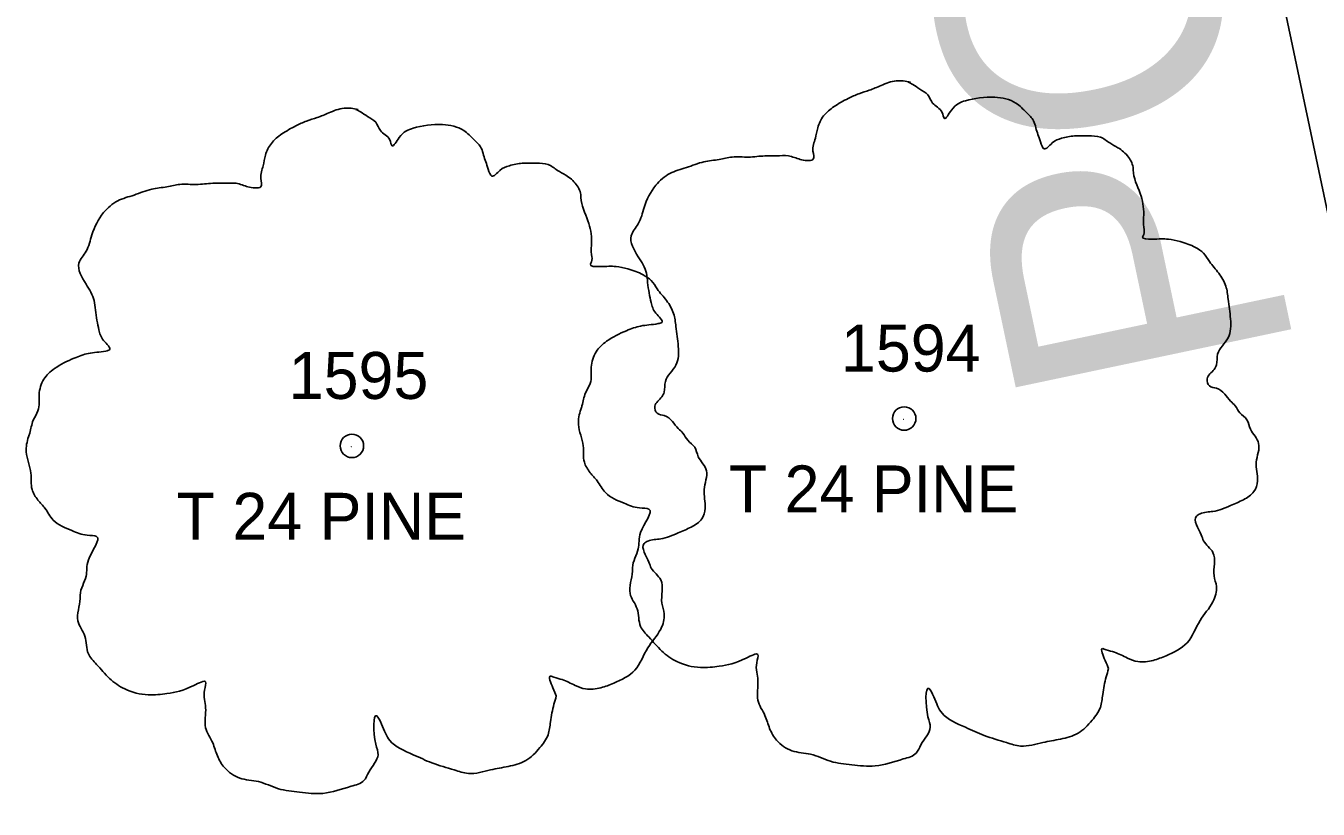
# Model space of a CAD drawing. Extents: x 1964982 to 1970452, y 1116335 to 1119906.
# Drawn here: x 1966642.81 to 1966670.35, y 1117477.18 to 1117493.86 of the extents above; entities that cross this region are included whole.
import ezdxf

# ---------------------------------------------------------------- set-up
doc = ezdxf.new("R2010")
doc.units = 0
for name, color, linetype in [('RD_EX_VEG', 7, 'Continuous'), ('RD_EX_VEG_txCode', 7, 'Continuous'), ('RD_HC_Data', 7, 'Continuous')]:
    doc.layers.add(name, color=color, linetype=linetype)

msp = doc.modelspace()

# ---------------------------------------------------------------- linework, layer by layer
at = {"layer": 'RD_EX_VEG'}
for centre, radius in [((1966661.529, 1117485.495), 0.25), ((1966661.529, 1117485.495), 0.25), ((1966661.516, 1117485.476), 0.0001), ((1966661.516, 1117485.476), 0.0001), ((1966649.762, 1117484.912), 0.25), ((1966649.762, 1117484.912), 0.25), ((1966649.749, 1117484.893), 0.0001), ((1966649.749, 1117484.893), 0.0001)]:
    msp.add_circle(centre, radius, dxfattribs=at)
for points in [[(1966661.661, 1117492.662), (1966661.361, 1117492.687), (1966661.036, 1117492.587), (1966660.786, 1117492.487), (1966660.561, 1117492.412), (1966660.336, 1117492.312), (1966660.036, 1117492.138), (1966659.811, 1117491.938), (1966659.686, 1117491.688), (1966659.636, 1117491.463), (1966659.586, 1117491.188), (1966659.586, 1117491.013), (1966659.462, 1117490.988), (1966659.312, 1117491.013), (1966659.062, 1117491.088), (1966658.812, 1117491.088), (1966658.562, 1117491.088), (1966658.212, 1117491.063), (1966657.862, 1117491.063), (1966657.587, 1117491.013), (1966657.262, 1117490.963), (1966656.888, 1117490.838), (1966656.538, 1117490.713), (1966656.238, 1117490.463), (1966655.988, 1117489.989), (1966655.863, 1117489.639), (1966655.713, 1117489.389), (1966655.863, 1117488.939), (1966656.038, 1117488.589), (1966656.063, 1117488.389), (1966656.138, 1117487.964), (1966656.238, 1117487.74), (1966656.363, 1117487.54), (1966656.288, 1117487.515), (1966655.913, 1117487.465), (1966655.613, 1117487.365), (1966655.188, 1117487.14), (1966654.963, 1117486.915), (1966654.863, 1117486.59), (1966654.839, 1117486.24), (1966654.739, 1117486.04), (1966654.664, 1117485.765), (1966654.639, 1117485.69), (1966654.589, 1117485.366), (1966654.689, 1117484.916), (1966654.714, 1117484.566), (1966654.839, 1117484.341), (1966654.988, 1117484.166), (1966655.163, 1117483.916), (1966655.563, 1117483.691), (1966655.888, 1117483.591), (1966656.088, 1117483.566), (1966655.913, 1117483.067), (1966655.863, 1117482.717), (1966655.738, 1117482.317), (1966655.738, 1117482.242), (1966655.688, 1117481.767), (1966655.838, 1117481.442), (1966655.913, 1117481.067), (1966656.088, 1117480.843), (1966656.363, 1117480.543), (1966656.688, 1117480.318), (1966657.188, 1117480.193), (1966657.587, 1117480.218), (1966658.162, 1117480.393), (1966658.412, 1117480.468), (1966658.387, 1117480.293), (1966658.412, 1117479.918), (1966658.412, 1117479.493), (1966658.562, 1117479.168), (1966658.662, 1117478.893), (1966658.812, 1117478.643), (1966659.137, 1117478.419), (1966659.536, 1117478.344), (1966659.961, 1117478.194), (1966660.411, 1117478.119), (1966660.911, 1117478.094), (1966661.511, 1117478.244), (1966661.785, 1117478.369), (1966661.885, 1117478.544), (1966662.085, 1117478.918), (1966662.035, 1117479.143), (1966662.06, 1117479.743), (1966662.16, 1117479.568), (1966662.335, 1117479.218), (1966662.835, 1117478.918), (1966663.235, 1117478.743), (1966663.71, 1117478.593), (1966664.01, 1117478.519), (1966664.484, 1117478.593), (1966664.859, 1117478.668), (1966665.234, 1117478.793), (1966665.534, 1117479.068), (1966665.709, 1117479.343), (1966665.759, 1117479.618), (1966665.834, 1117479.993), (1966665.884, 1117480.168)], [(1966661.661, 1117492.662), (1966661.361, 1117492.687), (1966661.036, 1117492.587), (1966660.786, 1117492.487), (1966660.561, 1117492.412), (1966660.336, 1117492.312), (1966660.036, 1117492.138), (1966659.811, 1117491.938), (1966659.686, 1117491.688), (1966659.636, 1117491.463), (1966659.586, 1117491.188), (1966659.586, 1117491.013), (1966659.462, 1117490.988), (1966659.312, 1117491.013), (1966659.062, 1117491.088), (1966658.812, 1117491.088), (1966658.562, 1117491.088), (1966658.212, 1117491.063), (1966657.862, 1117491.063), (1966657.587, 1117491.013), (1966657.262, 1117490.963), (1966656.888, 1117490.838), (1966656.538, 1117490.713), (1966656.238, 1117490.463), (1966655.988, 1117489.989), (1966655.863, 1117489.639), (1966655.713, 1117489.389), (1966655.863, 1117488.939), (1966656.038, 1117488.589), (1966656.063, 1117488.389), (1966656.138, 1117487.964), (1966656.238, 1117487.74), (1966656.363, 1117487.54), (1966656.288, 1117487.515), (1966655.913, 1117487.465), (1966655.613, 1117487.365), (1966655.188, 1117487.14), (1966654.963, 1117486.915), (1966654.863, 1117486.59), (1966654.839, 1117486.24), (1966654.739, 1117486.04), (1966654.664, 1117485.765), (1966654.639, 1117485.69), (1966654.589, 1117485.366), (1966654.689, 1117484.916), (1966654.714, 1117484.566), (1966654.839, 1117484.341), (1966654.988, 1117484.166), (1966655.163, 1117483.916), (1966655.563, 1117483.691), (1966655.888, 1117483.591), (1966656.088, 1117483.566), (1966655.913, 1117483.067), (1966655.863, 1117482.717), (1966655.738, 1117482.317), (1966655.738, 1117482.242), (1966655.688, 1117481.767), (1966655.838, 1117481.442), (1966655.913, 1117481.067), (1966656.088, 1117480.843), (1966656.363, 1117480.543), (1966656.688, 1117480.318), (1966657.188, 1117480.193), (1966657.587, 1117480.218), (1966658.162, 1117480.393), (1966658.412, 1117480.468), (1966658.387, 1117480.293), (1966658.412, 1117479.918), (1966658.412, 1117479.493), (1966658.562, 1117479.168), (1966658.662, 1117478.893), (1966658.812, 1117478.643), (1966659.137, 1117478.419), (1966659.536, 1117478.344), (1966659.961, 1117478.194), (1966660.411, 1117478.119), (1966660.911, 1117478.094), (1966661.511, 1117478.244), (1966661.785, 1117478.369), (1966661.885, 1117478.544), (1966662.085, 1117478.918), (1966662.035, 1117479.143), (1966662.06, 1117479.743), (1966662.16, 1117479.568), (1966662.335, 1117479.218), (1966662.835, 1117478.918), (1966663.235, 1117478.743), (1966663.71, 1117478.593), (1966664.01, 1117478.519), (1966664.484, 1117478.593), (1966664.859, 1117478.668), (1966665.234, 1117478.793), (1966665.534, 1117479.068), (1966665.709, 1117479.343), (1966665.759, 1117479.618), (1966665.834, 1117479.993), (1966665.884, 1117480.168)], [(1966665.884, 1117480.168), (1966665.809, 1117480.343), (1966665.759, 1117480.593), (1966665.834, 1117480.568), (1966666.009, 1117480.518), (1966666.284, 1117480.393), (1966666.508, 1117480.318), (1966666.833, 1117480.343), (1966667.108, 1117480.443), (1966667.558, 1117480.718), (1966667.833, 1117481.192), (1966668.108, 1117481.592), (1966668.183, 1117481.917), (1966668.133, 1117482.142), (1966668.108, 1117482.642), (1966667.908, 1117482.892), (1966667.858, 1117483.017), (1966667.758, 1117483.416), (1966667.833, 1117483.466), (1966668.108, 1117483.516), (1966668.483, 1117483.641), (1966668.757, 1117483.766), (1966668.982, 1117483.941), (1966669.057, 1117484.166), (1966669.032, 1117484.566), (1966669.082, 1117484.966), (1966669.007, 1117485.116), (1966668.907, 1117485.266), (1966668.832, 1117485.466), (1966668.682, 1117485.615), (1966668.583, 1117485.765), (1966668.483, 1117485.865), (1966668.358, 1117486.015), (1966668.183, 1117486.14), (1966668.033, 1117486.19), (1966667.983, 1117486.34), (1966668.133, 1117486.54), (1966668.183, 1117486.64), (1966668.208, 1117486.865), (1966668.433, 1117487.215), (1966668.483, 1117487.615), (1966668.433, 1117488.039), (1966668.383, 1117488.314), (1966668.233, 1117488.589), (1966668.033, 1117488.839), (1966667.908, 1117489.014), (1966667.733, 1117489.139), (1966667.408, 1117489.264), (1966667.158, 1117489.314), (1966666.808, 1117489.314), (1966666.608, 1117489.364), (1966666.633, 1117489.414), (1966666.633, 1117489.564), (1966666.633, 1117489.839), (1966666.558, 1117490.288), (1966666.408, 1117490.788), (1966666.408, 1117490.813), (1966666.308, 1117491.063), (1966666.084, 1117491.263), (1966665.909, 1117491.363), (1966665.709, 1117491.488), (1966665.459, 1117491.513), (1966665.159, 1117491.513), (1966664.884, 1117491.463), (1966664.684, 1117491.363), (1966664.509, 1117491.238), (1966664.434, 1117491.388), (1966664.334, 1117491.688), (1966664.284, 1117491.838), (1966664.134, 1117492.013), (1966663.91, 1117492.213), (1966663.46, 1117492.337), (1966662.835, 1117492.263), (1966662.535, 1117492.063), (1966662.385, 1117491.888), (1966662.335, 1117492.013), (1966662.135, 1117492.213), (1966662.035, 1117492.387), (1966661.86, 1117492.512), (1966661.711, 1117492.612), (1966661.611, 1117492.662)], [(1966665.884, 1117480.168), (1966665.809, 1117480.343), (1966665.759, 1117480.593), (1966665.834, 1117480.568), (1966666.009, 1117480.518), (1966666.284, 1117480.393), (1966666.508, 1117480.318), (1966666.833, 1117480.343), (1966667.108, 1117480.443), (1966667.558, 1117480.718), (1966667.833, 1117481.192), (1966668.108, 1117481.592), (1966668.183, 1117481.917), (1966668.133, 1117482.142), (1966668.108, 1117482.642), (1966667.908, 1117482.892), (1966667.858, 1117483.017), (1966667.758, 1117483.416), (1966667.833, 1117483.466), (1966668.108, 1117483.516), (1966668.483, 1117483.641), (1966668.757, 1117483.766), (1966668.982, 1117483.941), (1966669.057, 1117484.166), (1966669.032, 1117484.566), (1966669.082, 1117484.966), (1966669.007, 1117485.116), (1966668.907, 1117485.266), (1966668.832, 1117485.466), (1966668.682, 1117485.615), (1966668.583, 1117485.765), (1966668.483, 1117485.865), (1966668.358, 1117486.015), (1966668.183, 1117486.14), (1966668.033, 1117486.19), (1966667.983, 1117486.34), (1966668.133, 1117486.54), (1966668.183, 1117486.64), (1966668.208, 1117486.865), (1966668.433, 1117487.215), (1966668.483, 1117487.615), (1966668.433, 1117488.039), (1966668.383, 1117488.314), (1966668.233, 1117488.589), (1966668.033, 1117488.839), (1966667.908, 1117489.014), (1966667.733, 1117489.139), (1966667.408, 1117489.264), (1966667.158, 1117489.314), (1966666.808, 1117489.314), (1966666.608, 1117489.364), (1966666.633, 1117489.414), (1966666.633, 1117489.564), (1966666.633, 1117489.839), (1966666.558, 1117490.288), (1966666.408, 1117490.788), (1966666.408, 1117490.813), (1966666.308, 1117491.063), (1966666.084, 1117491.263), (1966665.909, 1117491.363), (1966665.709, 1117491.488), (1966665.459, 1117491.513), (1966665.159, 1117491.513), (1966664.884, 1117491.463), (1966664.684, 1117491.363), (1966664.509, 1117491.238), (1966664.434, 1117491.388), (1966664.334, 1117491.688), (1966664.284, 1117491.838), (1966664.134, 1117492.013), (1966663.91, 1117492.213), (1966663.46, 1117492.337), (1966662.835, 1117492.263), (1966662.535, 1117492.063), (1966662.385, 1117491.888), (1966662.335, 1117492.013), (1966662.135, 1117492.213), (1966662.035, 1117492.387), (1966661.86, 1117492.512), (1966661.711, 1117492.612), (1966661.611, 1117492.662)], [(1966649.894, 1117492.079), (1966649.594, 1117492.104), (1966649.269, 1117492.004), (1966649.019, 1117491.904), (1966648.794, 1117491.829), (1966648.569, 1117491.729), (1966648.269, 1117491.555), (1966648.045, 1117491.355), (1966647.92, 1117491.105), (1966647.87, 1117490.88), (1966647.82, 1117490.605), (1966647.82, 1117490.43), (1966647.695, 1117490.405), (1966647.545, 1117490.43), (1966647.295, 1117490.505), (1966647.045, 1117490.505), (1966646.795, 1117490.505), (1966646.445, 1117490.48), (1966646.095, 1117490.48), (1966645.821, 1117490.43), (1966645.496, 1117490.38), (1966645.121, 1117490.255), (1966644.771, 1117490.13), (1966644.471, 1117489.88), (1966644.221, 1117489.405), (1966644.096, 1117489.056), (1966643.946, 1117488.806), (1966644.096, 1117488.356), (1966644.271, 1117488.006), (1966644.296, 1117487.806), (1966644.371, 1117487.381), (1966644.471, 1117487.156), (1966644.596, 1117486.956), (1966644.521, 1117486.932), (1966644.146, 1117486.882), (1966643.846, 1117486.782), (1966643.422, 1117486.557), (1966643.197, 1117486.332), (1966643.097, 1117486.007), (1966643.072, 1117485.657), (1966642.972, 1117485.457), (1966642.897, 1117485.182), (1966642.872, 1117485.107), (1966642.822, 1117484.782), (1966642.922, 1117484.333), (1966642.947, 1117483.983), (1966643.072, 1117483.758), (1966643.222, 1117483.583), (1966643.397, 1117483.333), (1966643.796, 1117483.108), (1966644.121, 1117483.008), (1966644.321, 1117482.983), (1966644.146, 1117482.483), (1966644.096, 1117482.134), (1966643.971, 1117481.734), (1966643.971, 1117481.659), (1966643.921, 1117481.184), (1966644.071, 1117480.859), (1966644.146, 1117480.484), (1966644.321, 1117480.259), (1966644.596, 1117479.96), (1966644.921, 1117479.735), (1966645.421, 1117479.61), (1966645.821, 1117479.635), (1966646.395, 1117479.81), (1966646.645, 1117479.885), (1966646.62, 1117479.71), (1966646.645, 1117479.335), (1966646.645, 1117478.91), (1966646.795, 1117478.585), (1966646.895, 1117478.31), (1966647.045, 1117478.06), (1966647.37, 1117477.836), (1966647.77, 1117477.761), (1966648.194, 1117477.611), (1966648.644, 1117477.536), (1966649.144, 1117477.511), (1966649.744, 1117477.661), (1966650.019, 1117477.786), (1966650.119, 1117477.96), (1966650.319, 1117478.335), (1966650.269, 1117478.56), (1966650.294, 1117479.16), (1966650.393, 1117478.985), (1966650.568, 1117478.635), (1966651.068, 1117478.335), (1966651.468, 1117478.16), (1966651.943, 1117478.01), (1966652.243, 1117477.935), (1966652.717, 1117478.01), (1966653.092, 1117478.085), (1966653.467, 1117478.21), (1966653.767, 1117478.485), (1966653.942, 1117478.76), (1966653.992, 1117479.035), (1966654.067, 1117479.41), (1966654.117, 1117479.585)], [(1966649.894, 1117492.079), (1966649.594, 1117492.104), (1966649.269, 1117492.004), (1966649.019, 1117491.904), (1966648.794, 1117491.829), (1966648.569, 1117491.729), (1966648.269, 1117491.555), (1966648.045, 1117491.355), (1966647.92, 1117491.105), (1966647.87, 1117490.88), (1966647.82, 1117490.605), (1966647.82, 1117490.43), (1966647.695, 1117490.405), (1966647.545, 1117490.43), (1966647.295, 1117490.505), (1966647.045, 1117490.505), (1966646.795, 1117490.505), (1966646.445, 1117490.48), (1966646.095, 1117490.48), (1966645.821, 1117490.43), (1966645.496, 1117490.38), (1966645.121, 1117490.255), (1966644.771, 1117490.13), (1966644.471, 1117489.88), (1966644.221, 1117489.405), (1966644.096, 1117489.056), (1966643.946, 1117488.806), (1966644.096, 1117488.356), (1966644.271, 1117488.006), (1966644.296, 1117487.806), (1966644.371, 1117487.381), (1966644.471, 1117487.156), (1966644.596, 1117486.956), (1966644.521, 1117486.932), (1966644.146, 1117486.882), (1966643.846, 1117486.782), (1966643.422, 1117486.557), (1966643.197, 1117486.332), (1966643.097, 1117486.007), (1966643.072, 1117485.657), (1966642.972, 1117485.457), (1966642.897, 1117485.182), (1966642.872, 1117485.107), (1966642.822, 1117484.782), (1966642.922, 1117484.333), (1966642.947, 1117483.983), (1966643.072, 1117483.758), (1966643.222, 1117483.583), (1966643.397, 1117483.333), (1966643.796, 1117483.108), (1966644.121, 1117483.008), (1966644.321, 1117482.983), (1966644.146, 1117482.483), (1966644.096, 1117482.134), (1966643.971, 1117481.734), (1966643.971, 1117481.659), (1966643.921, 1117481.184), (1966644.071, 1117480.859), (1966644.146, 1117480.484), (1966644.321, 1117480.259), (1966644.596, 1117479.96), (1966644.921, 1117479.735), (1966645.421, 1117479.61), (1966645.821, 1117479.635), (1966646.395, 1117479.81), (1966646.645, 1117479.885), (1966646.62, 1117479.71), (1966646.645, 1117479.335), (1966646.645, 1117478.91), (1966646.795, 1117478.585), (1966646.895, 1117478.31), (1966647.045, 1117478.06), (1966647.37, 1117477.836), (1966647.77, 1117477.761), (1966648.194, 1117477.611), (1966648.644, 1117477.536), (1966649.144, 1117477.511), (1966649.744, 1117477.661), (1966650.019, 1117477.786), (1966650.119, 1117477.96), (1966650.319, 1117478.335), (1966650.269, 1117478.56), (1966650.294, 1117479.16), (1966650.393, 1117478.985), (1966650.568, 1117478.635), (1966651.068, 1117478.335), (1966651.468, 1117478.16), (1966651.943, 1117478.01), (1966652.243, 1117477.935), (1966652.717, 1117478.01), (1966653.092, 1117478.085), (1966653.467, 1117478.21), (1966653.767, 1117478.485), (1966653.942, 1117478.76), (1966653.992, 1117479.035), (1966654.067, 1117479.41), (1966654.117, 1117479.585)], [(1966654.117, 1117479.585), (1966654.042, 1117479.76), (1966653.992, 1117480.01), (1966654.067, 1117479.985), (1966654.242, 1117479.935), (1966654.517, 1117479.81), (1966654.742, 1117479.735), (1966655.066, 1117479.76), (1966655.341, 1117479.86), (1966655.791, 1117480.135), (1966656.066, 1117480.609), (1966656.341, 1117481.009), (1966656.416, 1117481.334), (1966656.366, 1117481.559), (1966656.341, 1117482.059), (1966656.141, 1117482.309), (1966656.091, 1117482.433), (1966655.991, 1117482.833), (1966656.066, 1117482.883), (1966656.341, 1117482.933), (1966656.716, 1117483.058), (1966656.991, 1117483.183), (1966657.216, 1117483.358), (1966657.29, 1117483.583), (1966657.266, 1117483.983), (1966657.315, 1117484.383), (1966657.241, 1117484.533), (1966657.141, 1117484.682), (1966657.066, 1117484.882), (1966656.916, 1117485.032), (1966656.816, 1117485.182), (1966656.716, 1117485.282), (1966656.591, 1117485.432), (1966656.416, 1117485.557), (1966656.266, 1117485.607), (1966656.216, 1117485.757), (1966656.366, 1117485.957), (1966656.416, 1117486.057), (1966656.441, 1117486.282), (1966656.666, 1117486.632), (1966656.716, 1117487.031), (1966656.666, 1117487.456), (1966656.616, 1117487.731), (1966656.466, 1117488.006), (1966656.266, 1117488.256), (1966656.141, 1117488.431), (1966655.966, 1117488.556), (1966655.641, 1117488.681), (1966655.391, 1117488.731), (1966655.041, 1117488.731), (1966654.842, 1117488.781), (1966654.867, 1117488.831), (1966654.867, 1117488.981), (1966654.867, 1117489.256), (1966654.792, 1117489.705), (1966654.642, 1117490.205), (1966654.642, 1117490.23), (1966654.542, 1117490.48), (1966654.317, 1117490.68), (1966654.142, 1117490.78), (1966653.942, 1117490.905), (1966653.692, 1117490.93), (1966653.392, 1117490.93), (1966653.117, 1117490.88), (1966652.917, 1117490.78), (1966652.742, 1117490.655), (1966652.667, 1117490.805), (1966652.568, 1117491.105), (1966652.518, 1117491.255), (1966652.368, 1117491.43), (1966652.143, 1117491.629), (1966651.693, 1117491.754), (1966651.068, 1117491.679), (1966650.768, 1117491.48), (1966650.618, 1117491.305), (1966650.568, 1117491.43), (1966650.368, 1117491.629), (1966650.269, 1117491.804), (1966650.094, 1117491.929), (1966649.944, 1117492.029), (1966649.844, 1117492.079)], [(1966654.117, 1117479.585), (1966654.042, 1117479.76), (1966653.992, 1117480.01), (1966654.067, 1117479.985), (1966654.242, 1117479.935), (1966654.517, 1117479.81), (1966654.742, 1117479.735), (1966655.066, 1117479.76), (1966655.341, 1117479.86), (1966655.791, 1117480.135), (1966656.066, 1117480.609), (1966656.341, 1117481.009), (1966656.416, 1117481.334), (1966656.366, 1117481.559), (1966656.341, 1117482.059), (1966656.141, 1117482.309), (1966656.091, 1117482.433), (1966655.991, 1117482.833), (1966656.066, 1117482.883), (1966656.341, 1117482.933), (1966656.716, 1117483.058), (1966656.991, 1117483.183), (1966657.216, 1117483.358), (1966657.29, 1117483.583), (1966657.266, 1117483.983), (1966657.315, 1117484.383), (1966657.241, 1117484.533), (1966657.141, 1117484.682), (1966657.066, 1117484.882), (1966656.916, 1117485.032), (1966656.816, 1117485.182), (1966656.716, 1117485.282), (1966656.591, 1117485.432), (1966656.416, 1117485.557), (1966656.266, 1117485.607), (1966656.216, 1117485.757), (1966656.366, 1117485.957), (1966656.416, 1117486.057), (1966656.441, 1117486.282), (1966656.666, 1117486.632), (1966656.716, 1117487.031), (1966656.666, 1117487.456), (1966656.616, 1117487.731), (1966656.466, 1117488.006), (1966656.266, 1117488.256), (1966656.141, 1117488.431), (1966655.966, 1117488.556), (1966655.641, 1117488.681), (1966655.391, 1117488.731), (1966655.041, 1117488.731), (1966654.842, 1117488.781), (1966654.867, 1117488.831), (1966654.867, 1117488.981), (1966654.867, 1117489.256), (1966654.792, 1117489.705), (1966654.642, 1117490.205), (1966654.642, 1117490.23), (1966654.542, 1117490.48), (1966654.317, 1117490.68), (1966654.142, 1117490.78), (1966653.942, 1117490.905), (1966653.692, 1117490.93), (1966653.392, 1117490.93), (1966653.117, 1117490.88), (1966652.917, 1117490.78), (1966652.742, 1117490.655), (1966652.667, 1117490.805), (1966652.568, 1117491.105), (1966652.518, 1117491.255), (1966652.368, 1117491.43), (1966652.143, 1117491.629), (1966651.693, 1117491.754), (1966651.068, 1117491.679), (1966650.768, 1117491.48), (1966650.618, 1117491.305), (1966650.568, 1117491.43), (1966650.368, 1117491.629), (1966650.269, 1117491.804), (1966650.094, 1117491.929), (1966649.944, 1117492.029), (1966649.844, 1117492.079)]]:
    msp.add_spline(points, degree=3, dxfattribs=at)
at = {"layer": 'RD_HC_Data'}
msp.add_line((1966684.871, 1117421.945), (1966664.447, 1117518.825), dxfattribs=at)

# ---------------------------------------------------------------- texts
at = {"layer": 'RD_EX_VEG_txCode'}
for s, p in [('1594', (1966660.182, 1117486.495)), ('1594', (1966660.182, 1117486.495)), ('1595', (1966648.415, 1117485.912)), ('1595', (1966648.415, 1117485.912)), ('T 24 PINE', (1966657.792, 1117483.495)), ('T 24 PINE', (1966657.792, 1117483.495)), ('T 24 PINE', (1966646.026, 1117482.912)), ('T 24 PINE', (1966646.026, 1117482.912))]:
    msp.add_text(s, height=1, dxfattribs=at).set_placement(p)
at = {"layer": 'RD_HC_Data'}
msp.add_text('PC=49+10.12', height=6, rotation=101.9047, dxfattribs=at).set_placement((1966669.912, 1117486.752))

doc.saveas('drawing.dxf')
